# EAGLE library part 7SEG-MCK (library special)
7-segment DISPLAY single cathode, 13 mm
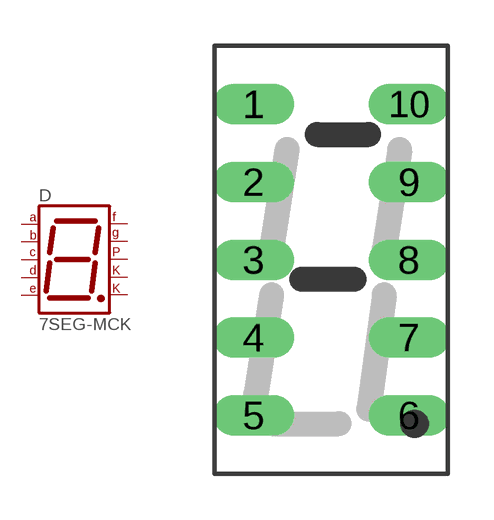
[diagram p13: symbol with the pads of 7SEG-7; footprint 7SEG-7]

Designator prefix D

## 7SEG-MCK  [7SEG-7]
1  CK1  pas
2  F  pas
3  G  pas
4  E  pas
5  D  pas
6  CK2  pas
7  DP  pas
8  C  pas
9  B  pas
10  A  pas

## Footprint 7SEG-7 (pad centres in mm)
7-segment DISPLAY 10 mm
drill 0.813 long: 1 -2.54,5.08; 2 -2.54,2.54; 3 -2.54,0; 4 -2.54,-2.54; 5 -2.54,-5.08; 6 2.54,-5.08; 7 2.54,-2.54; 8 2.54,0; 9 2.54,2.54; 10 2.54,5.08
